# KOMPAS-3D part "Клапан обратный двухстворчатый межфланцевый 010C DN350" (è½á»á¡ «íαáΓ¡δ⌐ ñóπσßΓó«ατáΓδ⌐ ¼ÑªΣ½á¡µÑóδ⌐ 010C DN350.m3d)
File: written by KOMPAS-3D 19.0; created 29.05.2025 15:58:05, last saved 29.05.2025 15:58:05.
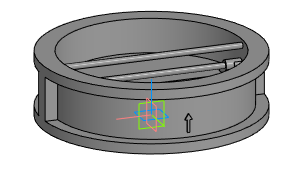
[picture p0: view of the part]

Document properties: Полное имя файла: E:\Dendor Работа Сачек\3D для проекитирвщиков\5.2 Тип 010C, 010C.Y Клапан обратный двухстворчатый межфланцевый\stp_Клапан обратный двухстворчатый межфланцевый 010C\Клапан обратный двухстворчатый межфланцевый 010C DN350.m3d

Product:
- Part/product: Клапан обратный двухстворчатый межфланцевый 010C DN350

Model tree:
1. Операция без истории:1  (labels: Клапан обратный двухстворчатый межфланцевый 010C DN350)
